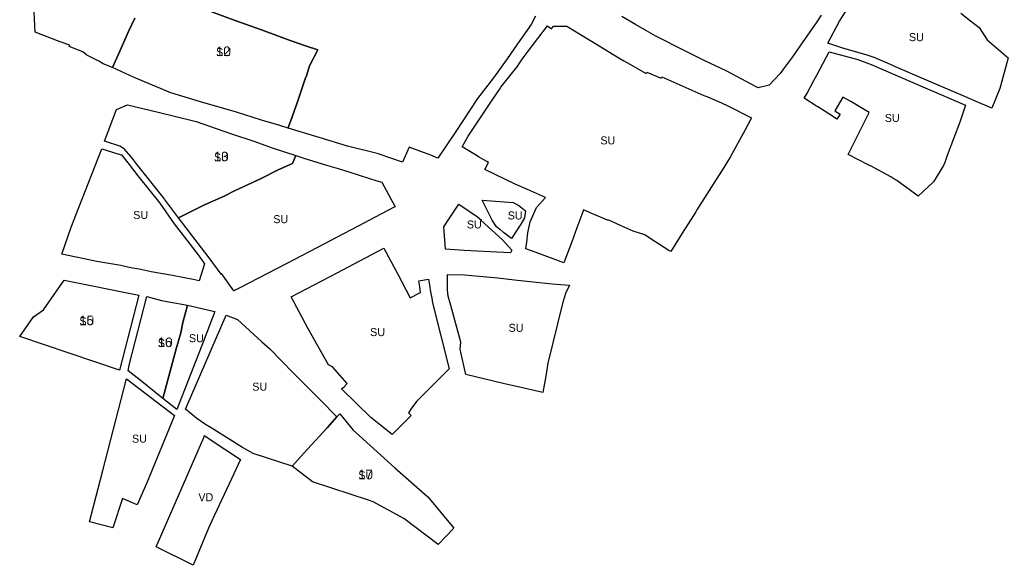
# Model space of a CAD drawing. Extents: x -545729 to -542727, y -1152416 to -1150952.
# Drawn here: x -544330 to -543713, y -1151631 to -1151290 of the extents above; entities that cross this region are included whole.
import ezdxf

# ---------------------------------------------------------------- set-up
doc = ezdxf.new("R2010")
doc.units = 0
for name, color, linetype in [('90480013', 7, 'Continuous'), ('90480023', 7, 'Continuous'), ('90590013', 7, 'Continuous'), ('ID_navrh', 7, 'Continuous')]:
    doc.layers.add(name, color=color, linetype=linetype)

msp = doc.modelspace()

# ---------------------------------------------------------------- linework, layer by layer
at = {"layer": '90480013'}
for points in [[(-544258.33, -1151289.17), (-544260.35, -1151293.51), (-544262.26, -1151297.41), (-544267.66, -1151309.79), (-544272.39, -1151320.03), (-544278.04, -1151317.64), (-544280.95, -1151316.12), (-544288.41, -1151312.26), (-544290.82, -1151310.16), (-544293.65, -1151309.1), (-544299.32, -1151306.86), (-544298.99, -1151306.02), (-544304.91, -1151303.91), (-544306.65, -1151303.34), (-544310.36, -1151301.85), (-544320.51, -1151297.8), (-544321.55, -1151281.26)], [(-544008.14, -1151287.81), (-544010.85, -1151293.16), (-544019.28, -1151305.09), (-544025.92, -1151314.56), (-544034.31, -1151326.51), (-544044.28, -1151339.37), (-544044.72, -1151339.94), (-544057.84, -1151359.95), (-544069.05, -1151376.63), (-544073.5, -1151374.74), (-544084.39, -1151370.83), (-544087.07, -1151369.74), (-544091.17, -1151379.24), (-544105.76, -1151374.17), (-544106.19, -1151374.05), (-544125.62, -1151369.07), (-544143.24, -1151363.76), (-544162.64, -1151357.91), (-544162.31, -1151356.97), (-544160.19, -1151350.9), (-544156.86, -1151341.35), (-544153.85, -1151332.74), (-544152.54, -1151328.97), (-544151.88, -1151327.08), (-544151.22, -1151325.19), (-544149.23, -1151318.84), (-544144.08, -1151308.97), (-544151.2, -1151306.59), (-544161.33, -1151303.12), (-544168.54, -1151300.36), (-544179.34, -1151296.45), (-544186.41, -1151293.9), (-544196.3, -1151290.32), (-544213.09, -1151284.25)], [(-543829.61, -1151287.29), (-543832.4, -1151291.37), (-543843.07, -1151306.73), (-543847.66, -1151313.33), (-543853.15, -1151320.78), (-543855.28, -1151323.64), (-543862.17, -1151331.05), (-543869.08, -1151332.76), (-543869.81, -1151332.37), (-543888.99, -1151322.05), (-543902.35, -1151315.81), (-543914.35, -1151309.77), (-543932.89, -1151300.45), (-543938.88, -1151297.05), (-543945.7, -1151293.07), (-543954.29, -1151288.01)], [(-543742.56, -1151286.1), (-543736.38, -1151290.88), (-543736.38, -1151290.88), (-543731, -1151295.03), (-543726.02, -1151302.63), (-543712.87, -1151314.04), (-543713.09, -1151314.85), (-543718.04, -1151333.17), (-543723.18, -1151345.39), (-543734.37, -1151340.55), (-543738.03, -1151338.97), (-543763.82, -1151327.87), (-543763.82, -1151327.87), (-543784.79, -1151318.85), (-543785.02, -1151318.75), (-543796.67, -1151313.74), (-543801, -1151312.35), (-543816.12, -1151307.9), (-543825.45, -1151304.75), (-543818.17, -1151291.08), (-543814.61, -1151285.21)]]:
    msp.add_lwpolyline(points, dxfattribs=at)
for points in [[(-544044.58, -1151375.21), (-544044.58, -1151375.21), (-544050.83, -1151371.43), (-544053.99, -1151369.58), (-544050.12, -1151362.83), (-544037.32, -1151343.5), (-544032.11, -1151335.76), (-544030.71, -1151333.78), (-544029.71, -1151332.33), (-544021.43, -1151321.93), (-544019.62, -1151319.47), (-544017.7, -1151316.73), (-544015.73, -1151313.95), (-544013.25, -1151310.54), (-544006.68, -1151301.94), (-544000.55, -1151294.01), (-543998.16, -1151295.82), (-543996.82, -1151294.06), (-543988.58, -1151294.17), (-543967.39, -1151307.03), (-543960.21, -1151311.44), (-543952.87, -1151315.73), (-543950.3, -1151317.23), (-543939.51, -1151323.53), (-543939.02, -1151323.8), (-543938.63, -1151322.99), (-543929.62, -1151326.64), (-543929.15, -1151325.78), (-543912.31, -1151333.42), (-543903, -1151337.4), (-543901.19, -1151338.19), (-543891.93, -1151342.09), (-543887.96, -1151343.87), (-543873.26, -1151351.49), (-543877.15, -1151358.86), (-543886.5, -1151376.12), (-543890.49, -1151382.44), (-543907.28, -1151409.04), (-543907.95, -1151410.1), (-543914.25, -1151420.05), (-543915.42, -1151421.9), (-543923.68, -1151434.92), (-543924.89, -1151434.32), (-543936.42, -1151426.93), (-543939.91, -1151424.52), (-543943.14, -1151423.47), (-543947.03, -1151422.21), (-543954.62, -1151418.97), (-543957.73, -1151417.48), (-543960.53, -1151416.15), (-543962.95, -1151415.13), (-543963.11, -1151415.49), (-543969.01, -1151412.99), (-543969.5, -1151412.77), (-543969.97, -1151412.56), (-543974.01, -1151410.75), (-543974.01, -1151410.75), (-543977.18, -1151409.33), (-543978.21, -1151408.89), (-543978.64, -1151410.19), (-543982.37, -1151420.14), (-543985.44, -1151428.89), (-543990.4, -1151442.09), (-544007.69, -1151435.61), (-544014.17, -1151433.33), (-544013.54, -1151429.19), (-544012.87, -1151423.32), (-544011.35, -1151416.47), (-544007.43, -1151407.53), (-544001.97, -1151401.33), (-544013.11, -1151396.34), (-544020.87, -1151392.94), (-544039.79, -1151383.71), (-544037.56, -1151379.31), (-544038.57, -1151378.83), (-544043.68, -1151375.75)], [(-543769.18, -1151400.33), (-543770.86, -1151399.11), (-543782.5, -1151390.66), (-543783.64, -1151389.9), (-543786.19, -1151388.37), (-543798.47, -1151381.64), (-543799.9, -1151380.94), (-543812.74, -1151374.27), (-543803.22, -1151355.28), (-543802.34, -1151353.53), (-543799.66, -1151348.17), (-543811.27, -1151341.32), (-543811.27, -1151341.32), (-543816.16, -1151338.44), (-543821.17, -1151347.08), (-543817.9, -1151349.21), (-543819.9, -1151352.3), (-543824.51, -1151349.2), (-543825, -1151348.89), (-543827.83, -1151347.05), (-543831.71, -1151344.67), (-543832.62, -1151344.1), (-543840.3, -1151339.22), (-543838.72, -1151336.43), (-543834.23, -1151328.1), (-543832.19, -1151324.27), (-543824.69, -1151310.23), (-543806.71, -1151314.94), (-543798.52, -1151318.03), (-543764.83, -1151332.61), (-543764.83, -1151332.61), (-543739.57, -1151343.55), (-543743.07, -1151354.05), (-543751.06, -1151374.9), (-543752.52, -1151379.28), (-543753.2, -1151381.33), (-543759.62, -1151391.46)], [(-544267.18, -1151443.7), (-544274.55, -1151442.49), (-544282.08, -1151441.25), (-544303.98, -1151436.74), (-544298.08, -1151419.85), (-544293.39, -1151407.59), (-544279.01, -1151370.9), (-544269.06, -1151373.86), (-544266.73, -1151374.66), (-544261.98, -1151380.65), (-544256.39, -1151387.69), (-544242.66, -1151404.79), (-544233.72, -1151417.75), (-544225.87, -1151427.83), (-544219.74, -1151436.02), (-544217.84, -1151438.56), (-544214.78, -1151442.66), (-544218.14, -1151453.31), (-544222.02, -1151452.57), (-544234.82, -1151450.04), (-544248.07, -1151447.62), (-544255.75, -1151446.11), (-544259.72, -1151445.33), (-544261.88, -1151444.9)], [(-544196.56, -1151459.57), (-544204.14, -1151448.78), (-544204.38, -1151449.08), (-544211.87, -1151438.99), (-544231.12, -1151413.87), (-544214.8, -1151405.86), (-544202.66, -1151400.37), (-544196.08, -1151397), (-544179.96, -1151389.48), (-544168.86, -1151384.01), (-544159.9, -1151379.99), (-544157.71, -1151374.97), (-544154.75, -1151375.93), (-544152.74, -1151376.56), (-544138.76, -1151381.03), (-544131.37, -1151383.21), (-544125.4, -1151384.89), (-544117.64, -1151387.42), (-544107.12, -1151390.8), (-544104.06, -1151391.7), (-544095.8, -1151407.09), (-544096.71, -1151407.57), (-544108.27, -1151413.61), (-544118.9, -1151419.16), (-544132.32, -1151426.21), (-544144.7, -1151432.67), (-544163.41, -1151442.49), (-544175.55, -1151448.78), (-544192.77, -1151457.73)], [(-544036.42, -1151435.27), (-544052.76, -1151434.33), (-544064.32, -1151433.53), (-544065.44, -1151419.66), (-544061.89, -1151414.18), (-544056.05, -1151405.45), (-544044.34, -1151413.42), (-544041.75, -1151415.34), (-544042.06, -1151415.69), (-544028.72, -1151427.75), (-544023, -1151434.1), (-544023.83, -1151435.74)], [(-544032.53, -1151419.55), (-544035.18, -1151415.37), (-544041.38, -1151402.95), (-544022.15, -1151404.34), (-544018.63, -1151406.23), (-544014.31, -1151409.66), (-544014.99, -1151414.04), (-544017.3, -1151417.97), (-544023.17, -1151426.97), (-544028.02, -1151423.22), (-544030.32, -1151421.02), (-544030.4, -1151421.15)], [(-544137.37, -1151505.81), (-544150.25, -1151482.96), (-544160.63, -1151463.23), (-544146.42, -1151455.75), (-544132.09, -1151448.33), (-544117.9, -1151440.85), (-544102.81, -1151432.82), (-544098.22, -1151441.35), (-544094.05, -1151449.25), (-544094.05, -1151449.25), (-544086.3, -1151463.91), (-544079.9, -1151460.53), (-544080.41, -1151457.13), (-544080.99, -1151453.26), (-544075.02, -1151452.28), (-544074.39, -1151456.12), (-544073.73, -1151460.18), (-544072.89, -1151464.18), (-544072.41, -1151466.98), (-544062.12, -1151508.24), (-544078.49, -1151524.76), (-544082.3, -1151528.55), (-544085.47, -1151532.93), (-544087.53, -1151535.79), (-544085.85, -1151537.43), (-544091.86, -1151543.49), (-544097.69, -1151549.46), (-544111, -1151538.73), (-544129.2, -1151520.88), (-544127.71, -1151519.63), (-544125.68, -1151517.57), (-544134.86, -1151507.04)], [(-544054.77, -1151491.65), (-544061.07, -1151468.84), (-544061.48, -1151467.29), (-544062.69, -1151462.83), (-544062.99, -1151459.16), (-544063.02, -1151449.37), (-544052.19, -1151449.68), (-544047.8, -1151449.94), (-544031.57, -1151451.4), (-544021.2, -1151452.61), (-544009.64, -1151453.87), (-544009.64, -1151453.87), (-543997.75, -1151455.17), (-543986.86, -1151456.12), (-543989.48, -1151461.15), (-543991.36, -1151467.47), (-544000.5, -1151504.81), (-544001.76, -1151512.89), (-544003.49, -1151523.2), (-544020.04, -1151519.34), (-544028.31, -1151517.41), (-544051.57, -1151511.96), (-544055.23, -1151495.99)], [(-544215.08, -1151490.07), (-544232.03, -1151533.8), (-544240.84, -1151526.96), (-544232.57, -1151495.79), (-544229.72, -1151485.92), (-544228.3, -1151479.39), (-544225.45, -1151468.6), (-544208.32, -1151472.48)], [(-544226.79, -1151533.59), (-544201.35, -1151474.81), (-544194.22, -1151477.43), (-544179.11, -1151491.44), (-544174.15, -1151495.92), (-544167.46, -1151502.76), (-544158.78, -1151511.45), (-544150.65, -1151519.52), (-544142.25, -1151528.08), (-544132.12, -1151538.41), (-544138.31, -1151545.2), (-544150.59, -1151558.64), (-544160.19, -1151569.12), (-544184.53, -1151561.26), (-544189.29, -1151558.54), (-544191.1, -1151557.51), (-544210.79, -1151545.24), (-544214.27, -1151543.1), (-544219.64, -1151539.31)], [(-544278.36, -1151571.97), (-544263.51, -1151514.56), (-544233.62, -1151537.42), (-544250.8, -1151579.54), (-544256.81, -1151593.28), (-544265.97, -1151589.28), (-544272.13, -1151607.7), (-544286.65, -1151603.93), (-544285.39, -1151599.09)]]:
    msp.add_lwpolyline(points, close=True, dxfattribs=at)
at = {"layer": '90480023'}
msp.add_lwpolyline([(-544213.09, -1151284.25), (-544196.3, -1151290.32), (-544186.41, -1151293.9), (-544179.34, -1151296.45), (-544168.54, -1151300.36), (-544161.33, -1151303.12), (-544151.2, -1151306.59), (-544144.08, -1151308.97), (-544149.23, -1151318.84), (-544151.22, -1151325.19), (-544151.88, -1151327.08), (-544152.54, -1151328.97), (-544153.85, -1151332.74), (-544156.86, -1151341.35), (-544160.19, -1151350.9), (-544162.31, -1151356.97), (-544162.64, -1151357.91), (-544168.36, -1151356.04), (-544179.22, -1151352.91), (-544194.96, -1151347.93), (-544217.39, -1151341.34), (-544235.8, -1151335.76), (-544258.81, -1151326.24), (-544272.39, -1151320.03), (-544267.66, -1151309.79), (-544262.26, -1151297.41), (-544260.35, -1151293.51), (-544258.33, -1151289.17)], dxfattribs=at)
for points in [[(-544179.96, -1151389.48), (-544196.08, -1151397), (-544202.66, -1151400.37), (-544214.8, -1151405.86), (-544231.12, -1151413.87), (-544239.84, -1151402.21), (-544240.13, -1151401.83), (-544257.27, -1151380.2), (-544259.92, -1151376.85), (-544260.9, -1151375.62), (-544264.92, -1151370.99), (-544265.13, -1151370.74), (-544267.72, -1151369.06), (-544276.72, -1151366.25), (-544277.27, -1151366.08), (-544269.78, -1151346.21), (-544263.04, -1151343.3), (-544243.82, -1151347.99), (-544221.72, -1151353.39), (-544220.07, -1151353.81), (-544197.92, -1151361.47), (-544184.06, -1151366.1), (-544171.97, -1151370.38), (-544157.71, -1151374.97), (-544159.9, -1151379.99), (-544168.86, -1151384.01)], [(-544267.95, -1151509.09), (-544330.23, -1151488.03), (-544321.64, -1151475.91), (-544315.45, -1151471.39), (-544302.52, -1151452.98), (-544255.94, -1151462.38)], [(-544255.11, -1151515.44), (-544262.51, -1151509.53), (-544261.82, -1151506.13), (-544250.9, -1151463.17), (-544241.72, -1151465.67), (-544225.45, -1151468.6), (-544228.3, -1151479.39), (-544229.72, -1151485.92), (-544232.57, -1151495.79), (-544240.84, -1151526.96)], [(-544111.73, -1151590.65), (-544147.45, -1151578.92), (-544160.19, -1151569.12), (-544150.59, -1151558.64), (-544138.31, -1151545.2), (-544132.12, -1151538.41), (-544130.43, -1151536.56), (-544122.04, -1151546.61), (-544118.11, -1151550.18), (-544096.05, -1151570.2), (-544075.47, -1151588.38), (-544059.11, -1151607.82), (-544068.93, -1151618.03), (-544090.42, -1151601.91), (-544109.43, -1151591.41)]]:
    msp.add_lwpolyline(points, close=True, dxfattribs=at)
at = {"layer": '90590013'}
msp.add_lwpolyline([(-544212.31, -1151607.99), (-544221.98, -1151631.1), (-544245, -1151619.57), (-544215.31, -1151551.2), (-544214.8, -1151550.04), (-544210, -1151553.26), (-544192.36, -1151565.06), (-544198.06, -1151577.18), (-544210.19, -1151603.35)], close=True, dxfattribs=at)

# ---------------------------------------------------------------- texts
at = {"layer": '90480013'}
for rotation, p in [(0, (-543774.89, -1151303.52)), (0, (-543789.94, -1151354.03)), (0, (-543967.62, -1151368.05)), (0, (-544259.38, -1151414.66)), (0, (-544171.9, -1151417.27)), (360, (-544025.46, -1151414.96)), (0, (-544051, -1151420.59)), (360, (-544024.94, -1151485.19)), (0, (-544224.58, -1151491.69)), (0, (-544111.38, -1151487.87)), (360, (-544185, -1151521.97)), (360, (-544260.13, -1151554.48))]:
    msp.add_text('SU', height=5, rotation=rotation, dxfattribs=at).set_placement(p)
at = {"layer": '90480023'}
for rotation, p in [(0, (-544207.59, -1151312.86)), (0, (-544208.92, -1151378.59)), (0, (-544293, -1151481.04)), (0, (-544243.98, -1151494.74)), (360, (-544118.79, -1151577.3))]:
    msp.add_text('SU', height=5, rotation=rotation, dxfattribs=at).set_placement(p)
at = {"layer": '90590013'}
msp.add_text('VD', height=5, rotation=0, dxfattribs=at).set_placement((-544218.68, -1151591.09))
at = {"layer": 'ID_navrh'}
for s, rotation, p in [('12', 0, (-544207.59, -1151312.86)), ('13', 360, (-544208.92, -1151378.59)), ('15', 0, (-544293, -1151481.04)), ('16', 360, (-544243.98, -1151494.74)), ('17', 360, (-544118.79, -1151577.3))]:
    msp.add_text(s, height=6, rotation=rotation, dxfattribs=at).set_placement(p)

doc.saveas('drawing.dxf')
